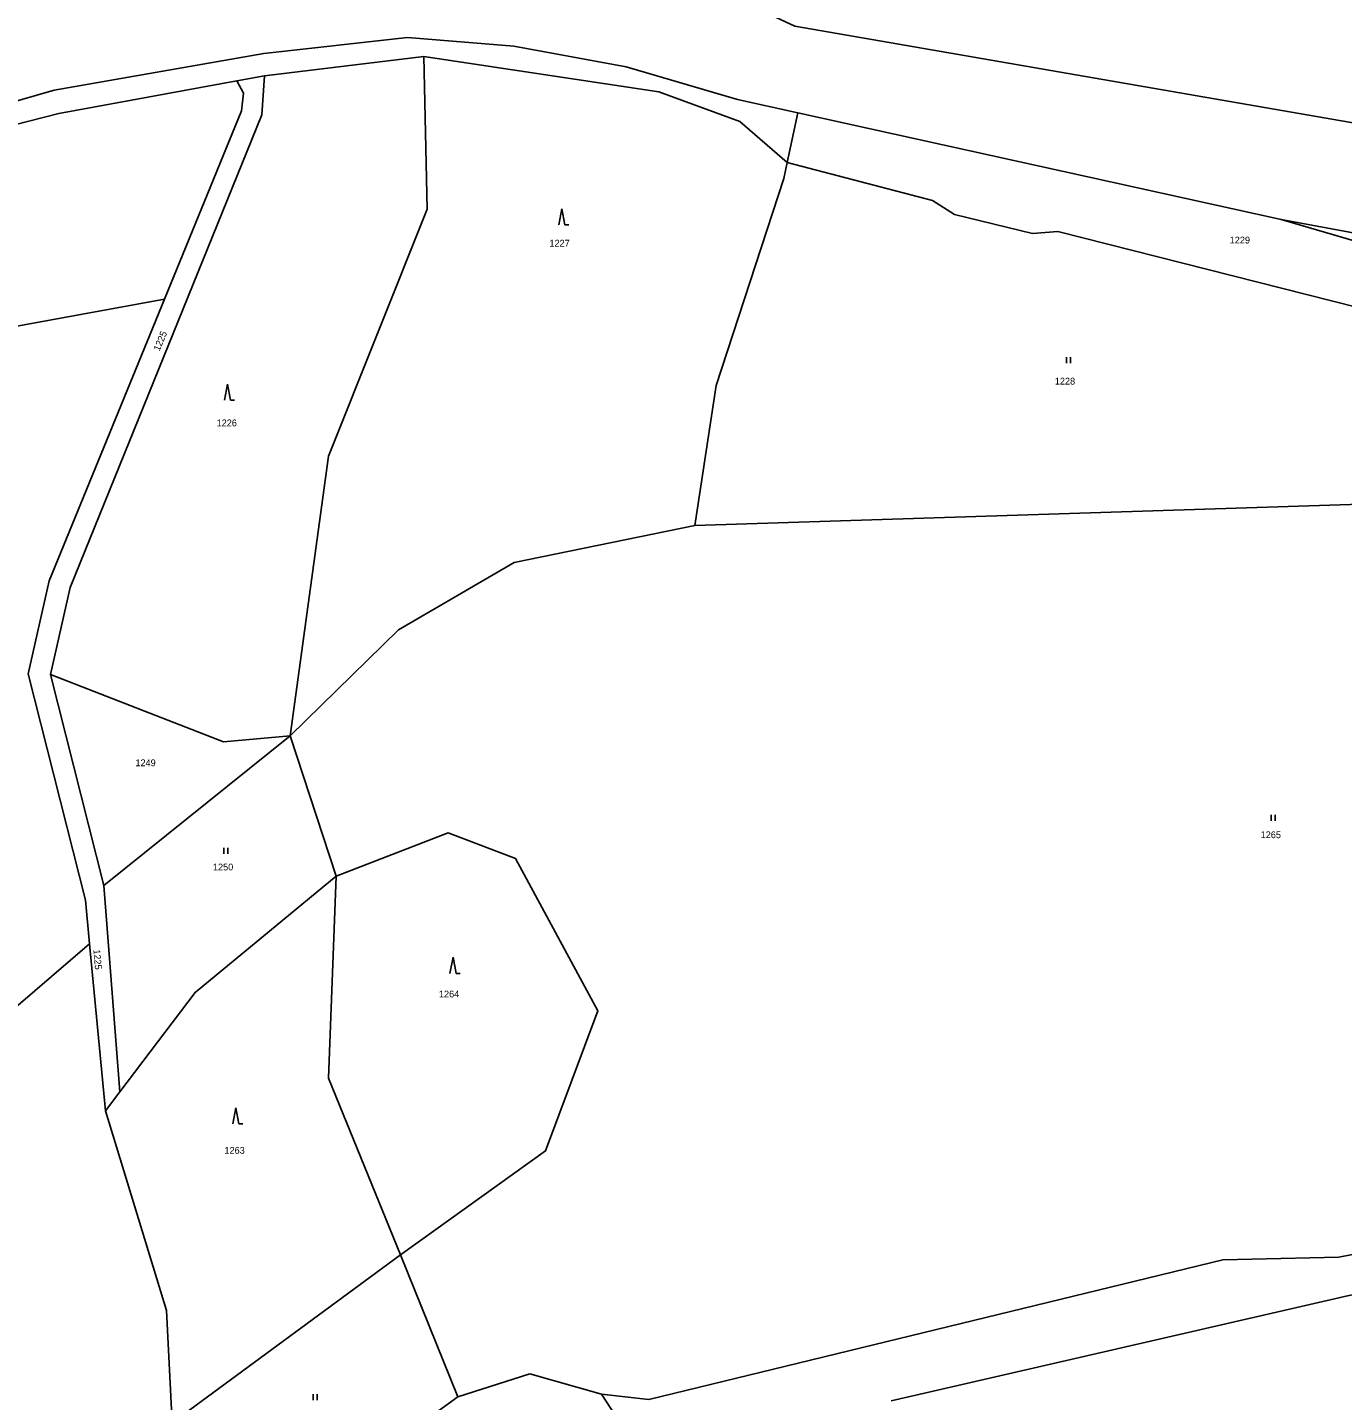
# Model space of a CAD drawing. Extents: x -520431 to -517205, y -1075927 to -1074013.
# Drawn here: x -518704.2 to -518376.5, y -1074942.1 to -1074599.9 of the extents above; entities that cross this region are included whole.
import ezdxf

# ---------------------------------------------------------------- set-up
doc = ezdxf.new("R2010")
doc.units = 0
for name, color, linetype in [('Hranice parcel', 7, 'Continuous'), ('Parcelní čísla', 7, 'Continuous'), ('Vrstva 54', 7, 'Continuous'), ('Značky kultur', 7, 'Continuous')]:
    doc.layers.add(name, color=color, linetype=linetype)

msp = doc.modelspace()

# ---------------------------------------------------------------- linework, layer by layer
at = {"layer": 'Hranice parcel'}
for p, q in [((-518605.42, -1074607.14), (-518645.08, -1074611.91)), ((-518645.08, -1074611.91), (-518652.03, -1074613.19)), ((-518512.21, -1074621.13), (-518514.87, -1074633.54)), ((-518512.21, -1074621.13), (-518391.78, -1074647.76)), ((-518762.22, -1074684.57), (-518670.06, -1074667.57)), ((-518685.13, -1074813.7), (-518698.43, -1074761.14)), ((-518685.13, -1074813.7), (-518638.74, -1074776.45)), ((-518627.24, -1074811.41), (-518638.74, -1074776.45)), ((-518681.17, -1074865.16), (-518685.13, -1074813.7)), ((-518820.43, -1074941.35), (-518688.69, -1074828.26)), ((-518688.69, -1074828.26), (-518684.73, -1074869.87)), ((-518684.73, -1074869.87), (-518681.17, -1074865.16)), ((-518668.09, -1074947.61), (-518611.24, -1074905.77)), ((-518611.24, -1074905.77), (-518596.9, -1074941.15))]:
    msp.add_line(p, q, dxfattribs=at)
for points in [[(-518655.84, -1074579.89), (-518655.92, -1074584.11), (-518559.23, -1074582.9), (-518540.09, -1074586.82), (-518512.95, -1074599.6), (-518319.13, -1074633.13), (-518291.79, -1074635.82), (-518220.74, -1074652.16), (-518160.18, -1074662.59)], [(-518859.92, -1074693.56), (-518818.11, -1074658.98), (-518790.98, -1074641.7), (-518732.82, -1074622.9), (-518726.06, -1074623.7), (-518697.52, -1074615.48), (-518645.27, -1074606.36), (-518609.5, -1074602.37), (-518582.97, -1074604.57), (-518554.94, -1074609.71), (-518527.23, -1074617.81), (-518512.21, -1074621.13)], [(-518638.74, -1074776.45), (-518629.15, -1074706.76), (-518604.54, -1074645.2), (-518605.42, -1074607.14)], [(-518514.87, -1074633.54), (-518526.62, -1074623.31), (-518546.86, -1074615.96), (-518605.42, -1074607.14)], [(-518698.43, -1074761.14), (-518693.52, -1074739.45), (-518645.78, -1074621.66), (-518645.08, -1074611.91)], [(-518652.03, -1074613.19), (-518696.33, -1074621.36), (-518722.44, -1074627.96)], [(-518670.06, -1074667.57), (-518650.87, -1074620.67), (-518650.36, -1074616.3), (-518652.03, -1074613.19)], [(-518537.85, -1074724), (-518532.54, -1074689.14), (-518515.72, -1074637.51), (-518514.87, -1074633.54)], [(-518195.48, -1074713.08), (-518210.7, -1074710.76), (-518329.06, -1074680.76), (-518447.41, -1074650.76), (-518453.72, -1074651.27), (-518473.14, -1074646.48), (-518478.66, -1074643), (-518514.87, -1074633.54)], [(-518391.78, -1074647.76), (-518209.04, -1074701.14), (-518180.42, -1074703.42), (-518170.2, -1074699.94)], [(-518164.12, -1074684.38), (-518293.1, -1074661.22), (-518322.7, -1074660.55), (-518391.78, -1074647.76)], [(-518670.06, -1074667.57), (-518698.79, -1074737.8), (-518704.03, -1074760.96), (-518689.73, -1074817.39), (-518688.69, -1074828.26)], [(-518537.85, -1074724), (-518366.66, -1074718.54), (-518195.48, -1074713.08)], [(-518638.74, -1074776.45), (-518611.74, -1074749.97), (-518582.92, -1074733.22), (-518537.85, -1074724)], [(-518698.43, -1074761.14), (-518655.31, -1074777.95), (-518638.74, -1074776.45)], [(-518611.24, -1074905.77), (-518575.07, -1074879.87), (-518562.01, -1074844.98), (-518582.52, -1074807), (-518599.37, -1074800.62), (-518627.24, -1074811.41)], [(-518681.17, -1074865.16), (-518662.42, -1074840.37), (-518627.24, -1074811.41)], [(-518611.24, -1074905.77), (-518629.15, -1074861.73), (-518627.24, -1074811.41)], [(-518561.09, -1074940.54), (-518549.3, -1074941.8), (-518406.31, -1074907.06), (-518377.4, -1074906.34), (-518279.09, -1074887.35), (-518129.08, -1074859.22), (-518119.27, -1074852.41), (-518117.54, -1074840.59)], [(-518488.98, -1074942.15), (-518375.2, -1074916), (-518252.8, -1074891.92), (-518160.47, -1074874.79), (-518153.83, -1074875.61), (-518134.22, -1074871.66), (-518128.73, -1074868.52), (-518116.84, -1074871.29), (-518110.95, -1074881.98)], [(-518684.73, -1074869.87), (-518669.52, -1074919.69), (-518668.09, -1074947.61)], [(-518596.9, -1074941.15), (-518578.99, -1074935.47), (-518561.09, -1074940.54)], [(-518561.09, -1074940.54), (-518551.81, -1074954.79), (-518584.27, -1074973.77), (-518601.76, -1074981.84)], [(-518622.68, -1074976.16), (-518616.71, -1074960.47), (-518609.29, -1074950.18), (-518596.9, -1074941.15)]]:
    msp.add_lwpolyline(points, dxfattribs=at)
at = {"layer": 'Vrstva 54'}
for points in [[(-519036.69, -1074860.75), (-519005.51, -1074823.73), (-519003.22, -1074810.58), (-518976.94, -1074776.6), (-518961.58, -1074753.12), (-518933.45, -1074719.94), (-518892.49, -1074678.08), (-518873.27, -1074665.82), (-518860.87, -1074659.24), (-518845, -1074648.92), (-518778.64, -1074615.13), (-518750.03, -1074593.5), (-518737.61, -1074584.11), (-518719.63, -1074584.91), (-518655.84, -1074579.89), (-518655.92, -1074584.11), (-518655.92, -1074584.11), (-518559.23, -1074582.9), (-518540.09, -1074586.82), (-518512.95, -1074599.6), (-518319.13, -1074633.13)], [(-518322.7, -1074660.55), (-518391.78, -1074647.76), (-518512.21, -1074621.13), (-518527.23, -1074617.81), (-518554.94, -1074609.71), (-518582.97, -1074604.57), (-518609.5, -1074602.37), (-518645.27, -1074606.36), (-518697.52, -1074615.48), (-518726.06, -1074623.7), (-518732.82, -1074622.9), (-518790.98, -1074641.7), (-518818.11, -1074658.98), (-518859.92, -1074693.56), (-518884.89, -1074716.72), (-518902.09, -1074734.26), (-518955.73, -1074797.05), (-519003.33, -1074855.22), (-519022.03, -1074880.42), (-519042.21, -1074912.15)]]:
    msp.add_lwpolyline(points, dxfattribs=at)
at = {"layer": 'Značky kultur'}
for p, q in [((-518570.98, -1074645.07), (-518571.73, -1074649.07)), ((-518570.23, -1074649.07), (-518570.98, -1074645.07)), ((-518570.23, -1074649.07), (-518569.23, -1074649.07)), ((-518445.24, -1074683.55), (-518445.24, -1074682.05)), ((-518444.24, -1074683.55), (-518444.24, -1074682.05)), ((-518654.33, -1074688.81), (-518655.08, -1074692.81)), ((-518653.58, -1074692.81), (-518654.33, -1074688.81)), ((-518653.58, -1074692.81), (-518652.58, -1074692.81)), ((-518394.26, -1074797.65), (-518394.26, -1074796.15)), ((-518393.26, -1074797.65), (-518393.26, -1074796.15)), ((-518655.2, -1074805.87), (-518655.2, -1074804.37)), ((-518654.2, -1074805.87), (-518654.2, -1074804.37)), ((-518598.13, -1074831.63), (-518598.88, -1074835.63)), ((-518597.38, -1074835.63), (-518598.13, -1074831.63)), ((-518597.38, -1074835.63), (-518596.38, -1074835.63)), ((-518652.26, -1074869.15), (-518653.01, -1074873.15)), ((-518651.51, -1074873.15), (-518652.26, -1074869.15)), ((-518651.51, -1074873.15), (-518650.51, -1074873.15)), ((-518633.01, -1074942.03), (-518633.01, -1074940.53)), ((-518632.01, -1074942.03), (-518632.01, -1074940.53))]:
    msp.add_line(p, q, dxfattribs=at)

# ---------------------------------------------------------------- texts
at = {"layer": 'Parcelní čísla'}
for s, p in [('1227', (-518574.1, -1074654.5)), ('1229', (-518404.58, -1074653.72)), ('1228', (-518448.16, -1074688.88)), ('1226', (-518657.04, -1074699.29)), ('1249', (-518677.27, -1074784)), ('1265', (-518396.87, -1074801.93)), ('1250', (-518657.95, -1074809.97)), ('1264', (-518601.63, -1074841.63)), ('1263', (-518655.08, -1074880.59))]:
    msp.add_text(s, height=1.7, dxfattribs=at).set_placement(p)
for rotation, p in [(67, (-518671.29, -1074680.67)), (275, (-518687.76, -1074829.73))]:
    msp.add_text('1225', height=1.7, rotation=rotation, dxfattribs=at).set_placement(p)

doc.saveas('drawing.dxf')
